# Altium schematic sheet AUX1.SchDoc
size A4
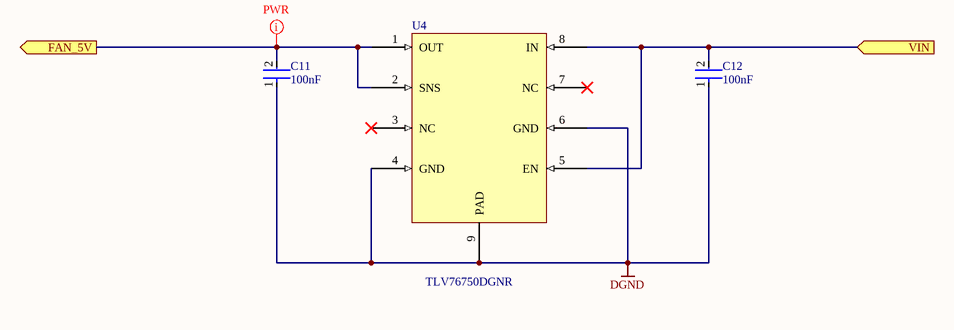
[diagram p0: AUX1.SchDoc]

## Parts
C11  value 100nF  [FP-CC0402-IPC_B]  (hidden comment: CC0402KRX7R9BB104)
C12  value 100nF  [FP-CC0402-IPC_B]  (hidden comment: CC0402KRX7R9BB104)
U4  TLV76750DGNR  [TLV76708DGNR-Footprint-1]

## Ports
FAN_5V (out), VIN (in)

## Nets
DGND: C11.1 C12.1 U4.4(GND) U4.6(GND) U4.9(PAD)
FAN_5V: C11.2 U4.1(OUT) U4.2(SNS) ; port FAN_5V
VIN: C12.2 U4.5(EN) U4.8(IN) ; port VIN

Not connected (* = marked no-connect by the designer): U4 3(NC)* 7(NC)*

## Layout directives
net class PWR: FAN_5V

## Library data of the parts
C11 C12 = CMP-x00152-1: Ceramic Capacitor, Multilayer, Ceramic, 50V, 10% +Tol, 10% -Tol, X7R, 15% TC, 0.1uF, Surface Mount, 0402
U4 = CMP-x00161-4: Adjustable- and fixed-output, 1-A, 16-V, positive-voltage low-dropout (LDO) linear regulator 8-HVSSOP -40 to 125; Manufacturer: TI; Template: TI_HVSSOP; Reel Width: 12mm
